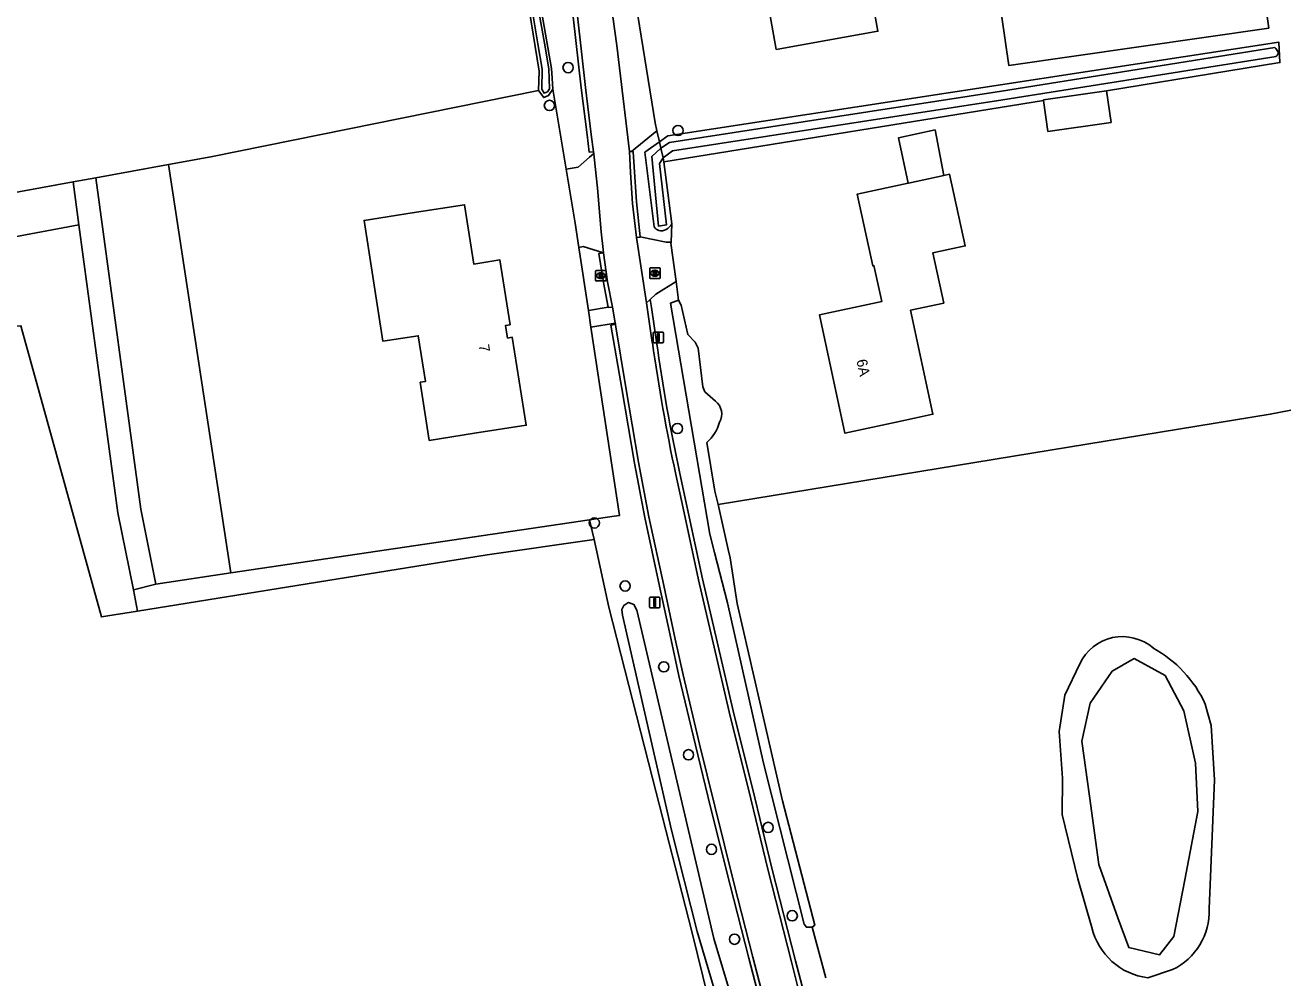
# Model space of a CAD drawing. Extents: x 162515 to 163909, y 388494 to 389773.
# Drawn here: x 163081.8 to 163201.7, y 389509.4 to 389600.1 of the extents above; entities that cross this region are included whole.
import ezdxf

# ---------------------------------------------------------------- set-up
doc = ezdxf.new("R2010")
doc.units = 0
for name, color, linetype in [('IMGEO_Afsluitpaal', 7, 'Continuous'), ('IMGEO_Boom', 7, 'Continuous'), ('IMGEO_Bouwland', 7, 'Continuous'), ('IMGEO_Brandkraan', 7, 'Continuous'), ('IMGEO_Erf', 7, 'Continuous'), ('IMGEO_Gemengd_bos', 7, 'Continuous'), ('IMGEO_Grasland_agrarisch', 7, 'Continuous'), ('IMGEO_Grasland_overig', 7, 'Continuous'), ('IMGEO_Groenvoorziening', 7, 'Continuous'), ('IMGEO_Meer_plas_ven_vijver', 7, 'Continuous'), ('IMGEO_Oever', 7, 'Continuous'), ('IMGEO_Pand', 7, 'Continuous'), ('IMGEO_Pand_nummerreeks', 7, 'Continuous'), ('IMGEO_Rijbaan_lokaal_gesloten', 7, 'Continuous'), ('IMGEO_Rijbaan_lokaal_halfverhard', 7, 'Continuous'), ('IMGEO_Rijbaan_lokaal_open', 7, 'Continuous'), ('IMGEO_Rioolput', 7, 'Continuous'), ('IMGEO_Verkeersbordpaal', 7, 'Continuous'), ('IMGEO_Voetpad_open', 7, 'Continuous'), ('IMGEO_Waterloop', 7, 'Continuous')]:
    doc.layers.add(name, color=color, linetype=linetype)

msp = doc.modelspace()

# ---------------------------------------------------------------- linework, layer by layer
at = {"layer": 'IMGEO_Afsluitpaal'}
for p, q in [((163141.77, 389570.89), (163142.56, 389570.89)), ((163142.56, 389570.89), (163141.77, 389570.89)), ((163141.67, 389569.99), (163141.67, 389570.79)), ((163141.67, 389570.79), (163141.67, 389569.99)), ((163142.56, 389569.89), (163141.77, 389569.89)), ((163141.77, 389569.89), (163142.56, 389569.89)), ((163142.66, 389570.79), (163142.66, 389569.99)), ((163142.66, 389569.99), (163142.66, 389570.79))]:
    msp.add_line(p, q, dxfattribs=at)
msp.add_lwpolyline([(163142.09, 389570.76), (163142.24, 389570.76), (163142.24, 389570.01), (163142.09, 389570.01), (163142.09, 389570.76)], dxfattribs=at)
for centre, start, end in [((163141.77, 389570.79), 90, 180), ((163141.77, 389570.79), 90, 180), ((163142.56, 389570.79), 0, 90), ((163142.56, 389570.79), 360, 90), ((163141.77, 389569.99), 180, 270), ((163141.77, 389569.99), 180, 270), ((163142.56, 389569.99), 270, 0), ((163142.56, 389569.99), 270, 0)]:
    msp.add_arc(centre, 0.1, start, end, dxfattribs=at)
at = {"layer": 'IMGEO_Boom'}
for centre in [(163133.57, 389596.09), (163131.79, 389592.49), (163144.04, 389590.1), (163143.98, 389561.72), (163136.07, 389552.72), (163139, 389546.72), (163142.68, 389539.02), (163145.04, 389530.65), (163152.62, 389523.73), (163147.23, 389521.64), (163154.92, 389515.32), (163149.43, 389513.08)]:
    msp.add_circle(centre, 0.489, dxfattribs=at)
at = {"layer": 'IMGEO_Bouwland'}
msp.add_lwpolyline([(163136.05, 389551.14), (163137.44, 389544.71), (163141.61, 389528.41), (163145.4, 389513.69), (163150.04, 389494.85)], dxfattribs=at)
at = {"layer": 'IMGEO_Brandkraan'}
for p, q in [((163136.19, 389575.84), (163136.19, 389576.69)), ((163136.27, 389576.77), (163137.12, 389576.77)), ((163137.12, 389575.77), (163136.27, 389575.77)), ((163136.68, 389576.55), (163136.71, 389576.55)), ((163136.7, 389575.99), (163136.68, 389575.99)), ((163137.19, 389576.69), (163137.19, 389575.84))]:
    msp.add_line(p, q, dxfattribs=at)
for points in [[(163136.19, 389575.84), (163136.19, 389576.69)], [(163136.27, 389576.77), (163137.12, 389576.77)], [(163137.12, 389575.77), (163136.27, 389575.77)], [(163136.54, 389576.47), (163136.54, 389576.07), (163136.75, 389576.07)], [(163136.77, 389576.47), (163136.54, 389576.47)], [(163136.72, 389576.39), (163136.67, 389576.39), (163136.67, 389576.31)], [(163136.67, 389576.31), (163136.72, 389576.31)], [(163136.73, 389576.23), (163136.67, 389576.23), (163136.67, 389576.15)], [(163136.67, 389576.15), (163136.73, 389576.15)], [(163137.19, 389576.69), (163137.19, 389575.84)]]:
    msp.add_lwpolyline(points, dxfattribs=at)
for centre, radius, start, end in [((163136.27, 389576.69), 0.0765, 91.552, 178.448), ((163136.27, 389576.69), 0.0765, 91.552, 178.448), ((163136.27, 389575.84), 0.0765, 181.552, 268.448), ((163136.27, 389575.84), 0.0765, 181.552, 268.448), ((163136.72, 389576.35), 0.0379, 267.8285, 90.9355), ((163136.73, 389576.19), 0.0404, 269.8759, 90.5077), ((163136.76, 389576.32), 0.251, 268.6676, 293.5347), ((163136.78, 389576.32), 0.145, 59.4692, 91.5367), ((163136.8, 389576.37), 0.0922, 285.5137, 58.1501), ((163136.81, 389576.18), 0.105, 301.3115, 78.989), ((163137.12, 389576.69), 0.0765, 1.552, 88.448), ((163137.12, 389576.69), 0.0765, 1.552, 88.448), ((163137.12, 389575.84), 0.0765, 271.552, 358.448), ((163137.12, 389575.84), 0.0765, 271.552, 358.448)]:
    msp.add_arc(centre, radius, start, end, dxfattribs=at)
for centre, major_axis, ratio, start_param, end_param in [((163136.68, 389576.27), (-0.387, 0.002), 0.722429, 4.712389, 7.853982), ((163136.7, 389576.27), (-0.39, 0.002), 0.717154, 1.570796, 4.712389)]:
    msp.add_ellipse(centre, major_axis=major_axis, ratio=ratio, start_param=start_param, end_param=end_param, dxfattribs=at)
at = {"layer": 'IMGEO_Erf'}
for points in [[(163142.27, 389589.02), (163143.07, 389589.58), (163201.3, 389598.51), (163201.38, 389596.57), (163184.87, 389593.87)], [(163130.74, 389593.91), (163131.25, 389593.23), (163131.71, 389593.43), (163132.1, 389594.03)], [(163178.87, 389592.95), (163142.7, 389587.12)], [(163142.7, 389587.12), (163143.46, 389581.22)]]:
    msp.add_lwpolyline(points, dxfattribs=at)
at = {"layer": 'IMGEO_Gemengd_bos'}
for points in [[(163088.57, 389585.6), (163095.49, 389586.85)], [(163101.43, 389547.96), (163095.49, 389586.85)], [(163101.43, 389547.96), (163094.3, 389546.91)]]:
    msp.add_lwpolyline(points, dxfattribs=at)
at = {"layer": 'IMGEO_Grasland_agrarisch'}
for points in [[(163130.74, 389593.91), (163130.82, 389595.75), (163129.49, 389604.01), (163127.31, 389615.89), (163124.17, 389630.54), (163122.35, 389637.11), (163120.08, 389643.72)], [(163095.49, 389586.85), (163099.54, 389587.59), (163130.74, 389593.91)], [(163209.16, 389564.77), (163200.47, 389563.08), (163147.85, 389554.47)], [(163183.48, 389514.21), (163182.14, 389518.84), (163180.64, 389524.96), (163180.67, 389528.43), (163180.37, 389532.87), (163180.89, 389536.32), (163182.33, 389539.32)], [(163194.27, 389535.48), (163194.84, 389533.42), (163195.14, 389528.26), (163194.64, 389515.98)], [(163191.15, 389510.19), (163188.81, 389509.41)]]:
    msp.add_lwpolyline(points, dxfattribs=at)
for centre, radius, start, end in [((163186.38, 389537.43), 4.47, 49.2424, 155.0268), ((163183.78, 389530.69), 11.53, 24.5344, 61.4338), ((163188.53, 389515.72), 6.12, 295.3433, 2.4123), ((163189.57, 389515.62), 6.26, 193.027, 262.9831)]:
    msp.add_arc(centre, radius, start, end, dxfattribs=at)
at = {"layer": 'IMGEO_Grasland_overig'}
for points in [[(163120.08, 389643.72), (163120.56, 389643.84), (163121.03, 389643.96), (163122.6, 389639.6), (163123.9, 389635.22), (163125.4, 389629.44), (163129.21, 389611.86), (163131.99, 389595.99), (163132.04, 389595.09), (163132.1, 389594.03)], [(163132.1, 389594.03), (163133.37, 389586.43)], [(163134.58, 389578.97), (163135.5, 389572.96)], [(163144.09, 389573.93), (163143.86, 389575.72)], [(163092.55, 389544.33), (163089.11, 389543.77), (163081.43, 389571.51), (163036.71, 389569.51)], [(163135.61, 389553.02), (163101.43, 389547.96)], [(163135.61, 389553.02), (163136.05, 389551.14)], [(163136.05, 389551.14), (163125.86, 389549.68), (163092.55, 389544.33)], [(163092.55, 389544.33), (163092.16, 389546.36)], [(163158.11, 389509.39), (163156.83, 389514.22)]]:
    msp.add_lwpolyline(points, dxfattribs=at)
at = {"layer": 'IMGEO_Groenvoorziening'}
for points in [[(163142.03, 389590.07), (163142.27, 389589.02)], [(163142.27, 389589.02), (163140.89, 389588.03), (163141.77, 389580.92)], [(163143.46, 389581.22), (163143.38, 389579.48)], [(163135.74, 389571.38), (163138.48, 389553.44), (163137.97, 389553.36), (163135.61, 389553.02)]]:
    msp.add_lwpolyline(points, dxfattribs=at)
for centre, radius, start, end in [((163142.45, 389581.35), 0.804, 212.9558, 252.6747), ((163142.46, 389581.54), 0.988, 255.0443, 297.1006), ((163142, 389582.1), 1.7, 302.3257, 329.0151)]:
    msp.add_arc(centre, radius, start, end, dxfattribs=at)
at = {"layer": 'IMGEO_Meer_plas_ven_vijver'}
msp.add_lwpolyline([(163190.47, 389538.2), (163192.24, 389534.82), (163193.36, 389529.84), (163193.58, 389525.24), (163192.32, 389518.74), (163191.27, 389513.35), (163189.91, 389511.58), (163186.99, 389512.28), (163185.96, 389515.12), (163184.13, 389520.19), (163183.23, 389526.7), (163182.51, 389531.93), (163183.31, 389535.55), (163185.4, 389538.6), (163187.49, 389539.81), (163190.47, 389538.2)], dxfattribs=at)
at = {"layer": 'IMGEO_Oever'}
for points in [[(163142.27, 389589.02), (163142.41, 389588.43)], [(163142.62, 389587.51), (163142.7, 389587.12)]]:
    msp.add_lwpolyline(points, dxfattribs=at)
at = {"layer": 'IMGEO_Pand'}
for points in [[(163154.82, 389618.32), (163159.58, 389619.17), (163160.12, 389616.18), (163163.66, 389616.81), (163164.79, 389610.48), (163161.25, 389609.85), (163163.08, 389599.55), (163158.32, 389598.71), (163153.4, 389597.83), (163149.9, 389617.44), (163154.82, 389618.32)], [(163198.61, 389611.71), (163200.32, 389599.85), (163175.56, 389596.29), (163173.86, 389608.15), (163198.61, 389611.71)], [(163184.87, 389593.87), (163178.86, 389593.01), (163178.87, 389592.95)], [(163184.87, 389593.87), (163185.3, 389590.87), (163179.29, 389590.01), (163178.87, 389592.95)], [(163165.98, 389585.09), (163165.04, 389589.4), (163168.54, 389590.16), (163169.36, 389585.82)], [(163169.36, 389585.82), (163169.92, 389585.94), (163171.4, 389579.11), (163168.33, 389578.45), (163169.36, 389573.67), (163166.18, 389572.98), (163168.33, 389563.07), (163164.84, 389562.32), (163159.95, 389561.26), (163157.51, 389572.53), (163163.46, 389573.82), (163162.71, 389577.24), (163162.6, 389577.21), (163161.12, 389584.04), (163165.98, 389585.09)], [(163165.98, 389585.09), (163166.01, 389585.1), (163169.36, 389585.82)], [(163124.64, 389561.26), (163129.58, 389562.03), (163128.24, 389570.41), (163127.81, 389570.33), (163127.61, 389571.53), (163128.04, 389571.6), (163127.07, 389577.78), (163124.58, 389577.38), (163123.7, 389583.03), (163118.72, 389582.26), (163114.13, 389581.54), (163115.92, 389570.03), (163119.29, 389570.55), (163119.97, 389566.2), (163119.48, 389566.12), (163120.34, 389560.59), (163124.64, 389561.26)]]:
    msp.add_lwpolyline(points, dxfattribs=at)
at = {"layer": 'IMGEO_Rijbaan_lokaal_gesloten'}
for points in [[(163130.01, 389624.59), (163131.24, 389619.38), (163132.17, 389614.98), (163133.3, 389609.2), (163133.91, 389605.25), (163134.45, 389600.99), (163135.22, 389594.21), (163135.78, 389589.73), (163135.99, 389588.08)], [(163139.43, 389588.1), (163138.22, 389598.19), (163137.34, 389604.37), (163136.22, 389611.66), (163135.21, 389617.1), (163135.2, 389617.13)], [(163135.99, 389588.08), (163136.01, 389587.92)], [(163136.01, 389587.92), (163136.05, 389587.57), (163136.36, 389584.6), (163136.72, 389580.44), (163136.9, 389578.76), (163136.94, 389578.44)], [(163140.09, 389579.9), (163139.71, 389583.14), (163139.5, 389586.1), (163139.43, 389588.1)], [(163141.05, 389573.69), (163140.09, 389579.9)], [(163136.94, 389578.44), (163137.33, 389575.7), (163137.81, 389573.28)], [(163137.81, 389573.28), (163137.84, 389573.12), (163138.05, 389571.74)], [(163141.59, 389569.92), (163141.05, 389573.69)], [(163138.05, 389571.74), (163138.07, 389571.65)], [(163138.07, 389571.65), (163138.07, 389571.6), (163139.08, 389565.61), (163140.29, 389558.5), (163141.26, 389553.32), (163142.68, 389546.78), (163143.78, 389541.67), (163144.52, 389538.25), (163146.1, 389531.66), (163147.54, 389525.76), (163149.39, 389518.33), (163151.18, 389511.37), (163152.16, 389507.6)], [(163156.58, 389504.03), (163155.47, 389508.5), (163154.85, 389510.93), (163152.59, 389519.76), (163150.76, 389527.36), (163149.01, 389534.33), (163147.39, 389541.31), (163145.99, 389547.31), (163144.52, 389554.12), (163143.82, 389557.35)]]:
    msp.add_lwpolyline(points, dxfattribs=at)
msp.add_arc((163317.19, 389594.49), 177.3, 187.9661, 192.092, dxfattribs=at)
at = {"layer": 'IMGEO_Rijbaan_lokaal_halfverhard'}
for points in [[(163129.62, 389624.5), (163130.85, 389619.29), (163131.78, 389614.91), (163132.9, 389609.13), (163133.52, 389605.2), (163134.05, 389600.94), (163134.82, 389594.16), (163135.39, 389589.68), (163135.59, 389588.03), (163135.99, 389588.08)], [(163139.61, 389588.09), (163139.78, 389588.07), (163140.07, 389583.3), (163140.43, 389579.97)], [(163136.94, 389578.44), (163136.49, 389578.38), (163136.94, 389575.62), (163137.39, 389573.26)], [(163137.81, 389573.28), (163137.4, 389573.23), (163137.39, 389573.26)], [(163141.99, 389569.98), (163141.52, 389573.25), (163141.4, 389574.01)], [(163152.16, 389507.6), (163151.77, 389507.5), (163150.79, 389511.27), (163149.01, 389518.23), (163147.15, 389525.66), (163145.71, 389531.56), (163144.13, 389538.16), (163143.39, 389541.59), (163142.29, 389546.69), (163140.87, 389553.24), (163139.89, 389558.42), (163138.68, 389565.54), (163137.64, 389571.56), (163138.07, 389571.65)], [(163156.58, 389504.03), (163156.99, 389504.14), (163155.86, 389508.6), (163155.23, 389511.03), (163152.98, 389519.86), (163151.14, 389527.46), (163149.4, 389534.42), (163147.78, 389541.4), (163146.38, 389547.39), (163144.91, 389554.2), (163144.21, 389557.44)]]:
    msp.add_lwpolyline(points, dxfattribs=at)
msp.add_arc((163317.45, 389594.54), 177.17, 187.9679, 192.0882, dxfattribs=at)
at = {"layer": 'IMGEO_Rijbaan_lokaal_open'}
for points in [[(163137.44, 389617.53), (163137.9, 389615.42), (163141.86, 389590.82), (163142.03, 389590.07)], [(163142.03, 389590.07), (163139.61, 389588.09)], [(163133.37, 389586.43), (163134.53, 389586.61), (163135.61, 389587.57), (163136.01, 389587.92)], [(163139.61, 389588.09), (163139.43, 389588.1)], [(163133.37, 389586.43), (163134.23, 389581.27), (163134.58, 389578.97)], [(163140.09, 389579.9), (163140.43, 389579.93), (163140.43, 389579.97)], [(163140.43, 389579.97), (163142.92, 389579.47), (163143.38, 389579.48)], [(163143.38, 389579.48), (163143.37, 389579.38), (163143.86, 389575.72)], [(163134.58, 389578.97), (163135.01, 389579.04), (163136.94, 389578.44)], [(163143.86, 389575.72), (163141.94, 389574.52), (163141.4, 389574.01)], [(163141.4, 389574.01), (163141.05, 389573.69)]]:
    msp.add_lwpolyline(points, dxfattribs=at)
at = {"layer": 'IMGEO_Rioolput'}
for p, q in [((163141.34, 389576.08), (163141.34, 389576.93)), ((163141.42, 389577.01), (163142.27, 389577.01)), ((163142.34, 389576.93), (163142.34, 389576.08)), ((163142.27, 389576.01), (163141.42, 389576.01)), ((163141.83, 389576.79), (163141.85, 389576.79)), ((163141.85, 389576.23), (163141.83, 389576.23))]:
    msp.add_line(p, q, dxfattribs=at)
for points in [[(163141.34, 389576.08), (163141.34, 389576.93)], [(163141.42, 389577.01), (163142.27, 389577.01)], [(163142.34, 389576.93), (163142.34, 389576.08)], [(163142.27, 389576.01), (163141.42, 389576.01)], [(163141.93, 389576.71), (163141.68, 389576.71), (163141.68, 389576.31)], [(163141.68, 389576.31), (163141.8, 389576.31), (163141.8, 389576.47), (163141.81, 389576.47)], [(163141.86, 389576.63), (163141.8, 389576.63), (163141.8, 389576.55)], [(163141.8, 389576.55), (163141.85, 389576.55)], [(163141.86, 389576.44), (163141.93, 389576.31), (163142.07, 389576.31), (163142.01, 389576.43)]]:
    msp.add_lwpolyline(points, dxfattribs=at)
for centre, radius, start, end in [((163141.42, 389576.93), 0.0765, 91.552, 178.448), ((163141.42, 389576.93), 0.0765, 91.552, 178.448), ((163142.27, 389576.93), 0.0765, 1.552, 88.448), ((163142.27, 389576.93), 0.0765, 1.552, 88.448), ((163141.42, 389576.08), 0.0765, 181.552, 268.448), ((163141.42, 389576.08), 0.0765, 181.552, 268.448), ((163141.81, 389576.42), 0.0533, 26.0293, 88.6989), ((163141.84, 389576.74), 0.19, 274.7715, 282.9687), ((163141.86, 389576.53), 0.0964, 77.0061, 93.1865), ((163141.88, 389576.59), 0.0378, 276.6634, 79.6772), ((163141.93, 389576.6), 0.109, 350.3612, 89.416), ((163141.93, 389576.6), 0.112, 277.5842, 350.9817), ((163141.91, 389576.38), 0.108, 29.5134, 73.7905), ((163142.27, 389576.08), 0.0765, 271.552, 358.448), ((163142.27, 389576.08), 0.0765, 271.552, 358.448)]:
    msp.add_arc(centre, radius, start, end, dxfattribs=at)
for centre, major_axis, ratio, start_param, end_param in [((163141.83, 389576.51), (-0.387, 0.002), 0.722429, 4.712389, 7.853982), ((163141.85, 389576.51), (-0.39, 0.002), 0.717154, 1.570796, 4.712389)]:
    msp.add_ellipse(centre, major_axis=major_axis, ratio=ratio, start_param=start_param, end_param=end_param, dxfattribs=at)
at = {"layer": 'IMGEO_Verkeersbordpaal'}
for p, q in [((163141.33, 389544.75), (163141.33, 389545.55)), ((163141.33, 389545.55), (163141.33, 389544.75)), ((163141.43, 389545.65), (163142.22, 389545.65)), ((163142.22, 389545.65), (163141.43, 389545.65)), ((163142.22, 389544.65), (163141.43, 389544.65)), ((163141.43, 389544.65), (163142.22, 389544.65)), ((163142.32, 389545.55), (163142.32, 389544.75)), ((163142.32, 389544.75), (163142.32, 389545.55))]:
    msp.add_line(p, q, dxfattribs=at)
msp.add_lwpolyline([(163141.75, 389545.52), (163141.9, 389545.52), (163141.9, 389544.77), (163141.75, 389544.77), (163141.75, 389545.52)], dxfattribs=at)
for centre, start, end in [((163141.43, 389545.55), 90, 180), ((163141.43, 389545.55), 90, 180), ((163141.43, 389544.75), 180, 270), ((163141.43, 389544.75), 180, 270), ((163142.22, 389545.55), 0, 90), ((163142.22, 389545.55), 360, 90), ((163142.22, 389544.75), 270, 0), ((163142.22, 389544.75), 270, 0)]:
    msp.add_arc(centre, 0.1, start, end, dxfattribs=at)
at = {"layer": 'IMGEO_Voetpad_open'}
for points in [[(163137.39, 389573.26), (163135.5, 389572.96)], [(163135.5, 389572.96), (163135.74, 389571.38)], [(163138.05, 389571.74), (163135.74, 389571.38)]]:
    msp.add_lwpolyline(points, dxfattribs=at)
at = {"layer": 'IMGEO_Waterloop'}
for points in [[(163130.53, 389602.87), (163131.31, 389598.43), (163131.72, 389595.98), (163131.79, 389594.07), (163131.59, 389593.78), (163131.28, 389593.65), (163131.06, 389594.03), (163131.1, 389595.93), (163130.7, 389598.35), (163129.96, 389602.78)], [(163200.91, 389598), (163174.85, 389593.85), (163143.22, 389588.95), (163142.41, 389588.43)], [(163142.62, 389587.51), (163143.53, 389588.15), (163174.98, 389593.01), (163201.02, 389597.16)], [(163142.62, 389587.51), (163142.29, 389586.97), (163142.95, 389581.13), (163142.17, 389580.99), (163141.53, 389587.63), (163142.41, 389588.43)], [(163142.41, 389588.43), (163142.62, 389587.51)], [(163086.4, 389585.2), (163088.57, 389585.6)], [(163094.3, 389546.91), (163092.85, 389554.05), (163088.57, 389585.6)], [(163031.16, 389573.65), (163038.45, 389575.02), (163070.03, 389580.97), (163070.11, 389582.24), (163086.4, 389585.2)], [(163086.96, 389581.13), (163086.4, 389585.2)], [(163036.29, 389571.61), (163086.96, 389581.13)], [(163086.96, 389581.13), (163090.68, 389553.68), (163092.16, 389546.36)], [(163156.83, 389514.22), (163156.27, 389514.22), (163156.07, 389514.5), (163152.2, 389529.84), (163148.74, 389545.12), (163147.51, 389549.92), (163147.06, 389551.67), (163143.33, 389573.67), (163144.09, 389573.93)], [(163144.09, 389573.93), (163144.33, 389573.46), (163144.98, 389570.67), (163145.67, 389569.95), (163145.95, 389569.37), (163146.39, 389565.7), (163146.58, 389565.22), (163147.61, 389564.32)], [(163146.78, 389560.38), (163147.56, 389555.75), (163147.85, 389554.47)], [(163147.85, 389554.47), (163148.82, 389550.2), (163149, 389549.41), (163149.68, 389545.04), (163153.99, 389526.27), (163157.09, 389514.41), (163156.83, 389514.22)], [(163092.16, 389546.36), (163094.3, 389546.91)], [(163150.88, 389497.95), (163150.59, 389498.21), (163150.43, 389498.5), (163149.97, 389500), (163145.86, 389513.8), (163143.43, 389523.47), (163138.76, 389543.95), (163138.69, 389544.49), (163138.87, 389544.87), (163139.27, 389545.12), (163139.31, 389545.14), (163139.84, 389544.96), (163140.11, 389544.42), (163147.45, 389513.15), (163151.39, 389500)]]:
    msp.add_lwpolyline(points, dxfattribs=at)
for centre, radius, start, end in [((163199.78, 389596.88), 1.59, 28.0114, 44.7887), ((163200.64, 389597.68), 0.646, 306.3118, 331.4696), ((163200.91, 389597.48), 0.311, 339.9795, 28.1595), ((163146.67, 389563.11), 1.53, 329.0767, 52.2942), ((163144.28, 389563.28), 3.83, 310.6875, 345.4449)]:
    msp.add_arc(centre, radius, start, end, dxfattribs=at)

# ---------------------------------------------------------------- texts
at = {"layer": 'IMGEO_Pand_nummerreeks'}
for s, rotation, p in [('7', 279.0477, (163125.04, 389569.66)), ('6A', 282.2095, (163161.03, 389568.21))]:
    msp.add_text(s, height=1, rotation=rotation, dxfattribs=at).set_placement(p)

doc.saveas('drawing.dxf')
